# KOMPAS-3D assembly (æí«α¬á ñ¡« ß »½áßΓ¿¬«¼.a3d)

Referenced files in D:\МОДЕЛЬ ТАНКА Т90\ДЕТАЛИ\КОРПУС\МЕТАЛЛ\КОРПУС ЛИТОЙ\: дно корпус.m3d
Referenced files in D:\МОДЕЛЬ ТАНКА Т90\ДЕТАЛИ\КОРПУС\МЕТАЛЛ\КОРПУС ШТАМПОВКА\ПЛАСТИК\: пластик дно.m3d
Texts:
  Сборка дно корпус с пластиком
